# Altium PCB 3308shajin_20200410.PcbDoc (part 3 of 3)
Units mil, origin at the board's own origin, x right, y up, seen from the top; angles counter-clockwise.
Board outline 4724.41 x 2952.76 mil, 4 copper layers (Top, GND, Power, Bottom), stack 35.4 mil thick; 266 components, 266 nets, 1212 pads, 1516 vias.
Unrouted connection lines stored in the file: 149.
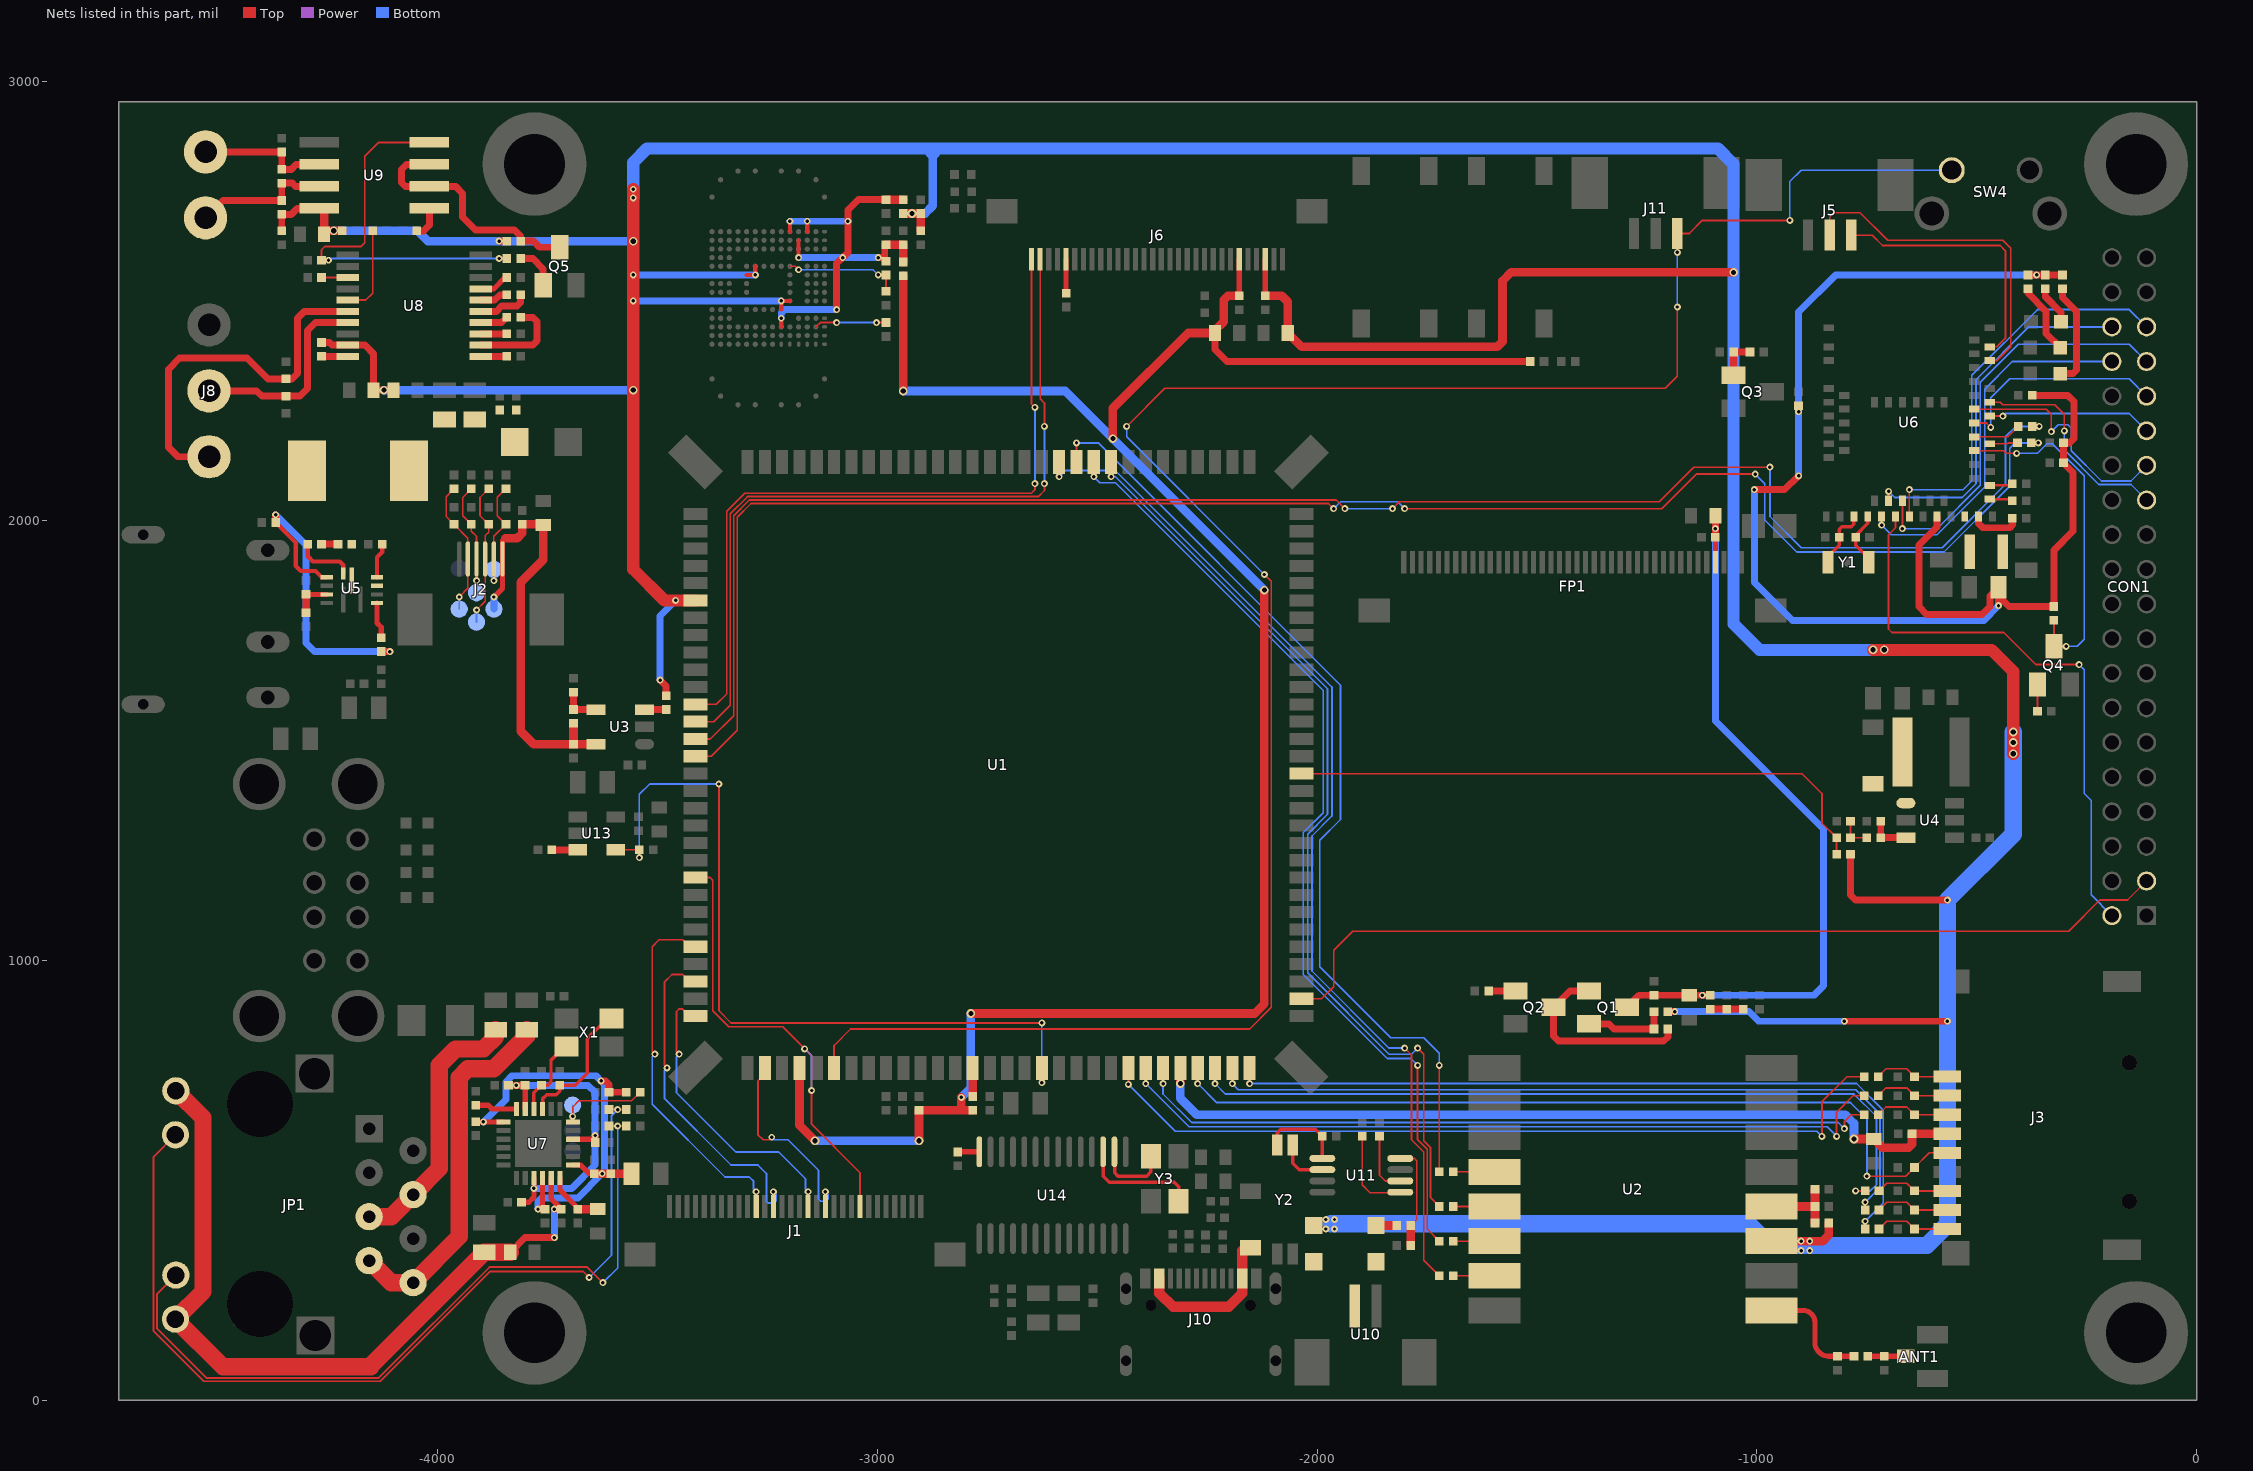
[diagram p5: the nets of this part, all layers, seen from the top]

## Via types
v1: diameter 15.75, hole 7.87, Top to Bottom, 1478 vias
v2: diameter 19.68, hole 11.81, Top to Bottom, 38 vias

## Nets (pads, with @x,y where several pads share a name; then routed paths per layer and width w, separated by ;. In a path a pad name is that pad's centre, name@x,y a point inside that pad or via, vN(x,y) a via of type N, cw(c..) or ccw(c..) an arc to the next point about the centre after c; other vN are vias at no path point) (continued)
MICP5: J1.11 U1.86 | length 837.2
  Top w3.94: v1(-3505.91,787.4) -3511.81,793.31 -3511.81,1031.83 -3496.4,1047.24 -3442.91,1047.24 -3427.17,1031.5 U1.86@-3413.39,1031.5 ; J1.11@-3275.59,440.94 v1(-3275.59,474.41)
  Bottom w3.94: v1(-3505.91,787.4) -3511.81,781.5 -3511.81,673.23 -3346.46,507.87 -3291.34,507.87 -3281.5,498.03 -3281.5,480.31 v1(-3275.59,474.41)
MICP6: J1.13 U1.88 | length 801.9
  Top w3.94: v1(-3478.35,755.91) -3484.25,761.81 -3484.25,951.13 -3466.87,968.5 -3442.91,968.5 -3427.17,952.76 U1.88@-3413.39,952.76 ; J1.13@-3236.22,440.94 v1(-3236.22,474.41)
  Bottom w3.94: v1(-3478.35,755.91) -3484.25,750 -3484.25,687.01 -3332.68,535.43 -3271.65,535.43 -3251.97,515.75 -3251.97,452.08 -3248.71,448.82 -3235.54,448.82 -3230.31,454.05 -3230.31,468.5 v1(-3236.22,474.41)
MICP7: J1.17 U1.90 | length 681.4
  Top w3.94: v1(-3450.79,787.4) -3456.69,793.31 -3456.69,884.26 -3451.19,889.76 -3442.91,889.76 -3427.17,874.02 U1.90@-3413.39,874.02 ; J1.17@-3157.48,440.94 v1(-3157.48,474.41)
  Bottom w3.94: v1(-3450.79,787.4) -3456.69,781.5 -3456.69,699.63 -3322.02,564.96 -3224.41,564.96 -3163.39,503.94 -3163.39,480.31 v1(-3157.48,474.41)
MICP8: J1.19 U1.92 | length 478
  Top w3.94: U1.92@-3255.91,755.91 -3255.91,742.13 -3271.65,726.38 -3271.65,604.33 -3259.84,592.52 -3246.06,592.52 v1(-3240.16,598.43) ; J1.19@-3118.11,440.94 v1(-3118.11,474.41)
  Bottom w3.94: v1(-3240.16,598.43) -3234.25,592.52 -3203.09,592.52 -3133.86,523.28 -3133.86,457.99 -3128.63,452.76 -3117.43,452.76 -3112.2,457.99 -3112.2,468.5 v1(-3118.11,474.41)
N18628326: R87.2 U14.14 | length 48.9
  Top w11.81: R87.2@-2816.93,564.96 -2816.54,565.35 U14.14@-2768.23,565.35
N18801307: R83.2 U13.3 | length 59.1
  Top w15.75: R83.2@-3740.16,1251.97 U13.3@-3681.1,1251.97
N20842578: Q2.1 R6.1 | length 61
  Top w15.75: R6.1@-1610.24,931.1 Q2.1@-1549.21,931.1
N20842606: Q1.1 Q2.3 R5.2 | length 447.7
  Top w15.75: Q1.1@-1381.89,931.1 -1425.2,931.1 Q2.3@-1462.6,893.7 -1462.6,828.74 -1450.79,816.93 -1212.6,816.93 -1202.76,826.77 R5.2@-1202.76,844.49
N20842653: Q1.2 R4.2 R5.1 | length 191.9
  Top w15.75: Q1.2@-1381.89,856.3 -1336.61,856.3 -1324.8,844.49 R5.1@-1234.25,844.49 R4.2@-1234.25,883.86
N77997198: D7.1 J3.8 R25.2 | length 169.5
  Top w3.94: R25.2@-722.44,433.07 -704.77,450.74 -659.45,450.74 D7.1@-641.78,433.07 J3.8@-567.54,433.07
N77997238: D6.1 J3.9 R26.2 | length 169.6
  Top w3.94: R26.2@-722.44,389.76 -704.72,407.48 -659.5,407.48 D6.1@-641.78,389.76 J3.9@-567.54,389.76
N77997484: D10.1 J3.3 R23.2 | length 171.5
  Top w3.94: R23.2@-724.41,649.61 -706.69,667.32 -659.5,667.32 D10.1@-641.78,649.61 J3.3@-567.54,649.61
N77997488: D12.1 J3.1 R21.2 | length 171.5
  Top w3.94: R21.2@-724.41,736.22 -706.69,753.94 -659.5,753.94 D12.1@-641.78,736.22 J3.1@-567.54,736.22
N77997499: D11.1 J3.2 R22.2 | length 171.5
  Top w3.94: R22.2@-724.41,692.91 -706.69,710.63 -659.5,710.63 D11.1@-641.78,692.91 J3.2@-567.54,692.91
N77997513: D8.1 J3.7 R24.2 | length 169.6
  Top w3.94: R24.2@-722.44,476.38 -704.72,494.09 -659.5,494.09 D8.1@-641.78,476.38 J3.7@-567.54,476.38
N80390256: D3.1 J2.5 P5.1 R14.2 | length 261.9
  Top w3.94: v1(-3872.05,1864.17) -3872.05,1912.43 J2.5@-3872.05,1913.39 -3872.05,1964.61 D3.1@-3844.49,1992.17 -3864.13,2011.81 -3864.13,2053.2 R14.2@-3844.49,2072.83
  Bottom w3.94: v1(-3872.05,1864.17) P5.1@-3872.05,1889.76
N80390258: D5.1 J2.4 P4.1 R12.2 | length 330.9
  Top w3.94: v1(-3911.42,1797.24) -3891.73,1816.93 -3891.73,1911.42 J2.4@-3891.73,1913.39 -3891.73,1966.54 -3883.86,1974.41 D5.1@-3883.86,1992.17 -3903.54,2011.86 -3903.54,2053.15 R12.2@-3883.86,2072.83
  Bottom w3.94: P4.1@-3911.42,1769.68 v1(-3911.42,1797.24)
N80390260: D4.1 J2.3 P3.1 R13.2 | length 257.4
  Top w3.94: R13.2@-3923.23,2072.83 -3942.91,2053.15 -3942.91,2011.86 D4.1@-3923.23,1992.17 -3923.23,1976.38 -3911.42,1964.57 J2.3@-3911.42,1913.39 -3911.42,1903.54 v1(-3911.42,1864.17)
  Bottom w3.94: P3.1@-3911.42,1836.61 v1(-3911.42,1864.17)
N80390262: D2.1 J2.2 P2.1 R11.2 | length 309.5
  Top w3.94: R11.2@-3962.6,2072.83 -3980.31,2055.12 -3980.31,2009.89 D2.1@-3962.6,1992.17 -3931.1,1960.68 -3931.1,1846.46 v1(-3950.79,1826.77)
  Bottom w3.94: P2.1@-3950.79,1799.21 v1(-3950.79,1826.77)
N80390735: CD3.2 RD1.1 RD2.1 U2.4 | length 175.2
  Top w19.68: U2.4@-966.54,440.94 CD3.2@-868.11,440.94 ; RD1.1@-868.11,403.54 CD3.2@-868.11,440.94 ; RD2.1@-868.11,480.31 CD3.2@-868.11,440.94
N80390797: ANT1.1 CD1.2 RW1.2 | length 86.6
  Top w11.81: RW1.2@-748.03,100.39 ANT1.1@-661.42,100.39
N80390810: CD2.2 RW1.1 U2.1 | length 266
  Top w11.81: U2.1@-966.54,204.72 -895.67,204.72 cw(c-895.67,177.17) -868.11,177.17 -868.11,131.89 ccw(c-836.61,131.89) -836.61,100.39 RW1.1@-779.53,100.39
N80390865: RW5.1 U2.12 | length 94.5
  Top w3.94: RW5.1@-1690.94,519.68 U2.12@-1596.46,519.68
N80390867: RW3.1 U2.14 | length 94.5
  Top w3.94: RW3.1@-1690.94,362.2 U2.14@-1596.46,362.2
N80390869: RW4.1 U2.13 | length 94.5
  Top w3.94: RW4.1@-1690.94,440.94 U2.13@-1596.46,440.94
N80390871: RW2.1 U2.15 | length 94.5
  Top w3.94: RW2.1@-1690.94,283.46 U2.15@-1596.46,283.46
N80396336: C18.1 R27.2 | length 37.4
  Top w15.75: R27.2@-4263.78,1946.85 C18.1@-4226.38,1946.85
N80396542: C20.1 C21.1 C22.1 C23.1 L2.2 R28.2 U5.5
N80396560: R29.1 R30.2 U5.11 | length 88.6
  Top w11.81: R30.2@-4299.21,1832.68 U5.11@-4251.97,1832.68
  Top w15.75: R29.1@-4299.21,1791.34 R30.2@-4299.21,1832.68
N80396572: C18.2 L2.1 U5.7
N80396580: R27.1 U5.8 | length 136.1
  Top w9.84: R27.1@-4295.28,1946.85 -4295.28,1919.29 -4283.46,1907.48 -4222.44,1907.48 -4214.57,1899.61 U5.8@-4214.57,1879.92
N80396618: R33.2 U5.3 | length 82.8
  Top w11.81: U5.3@-4137.8,1812.99 -4137.8,1767.72 -4127.95,1757.87 R33.2@-4127.95,1734.25
N80396635: C25.1 R33.1 U5.9 | length 755
  Top w9.84: C25.1@-4368.11,1996.06 -4322.83,1950.79 -4322.83,1897.64 -4311.02,1885.83 -4277.56,1885.83 -4263.78,1872.05 U5.9@-4251.97,1872.05
  Top w15.75: C25.1@-4368.11,1996.06 v1(-4368.11,2013.78) ; R33.1@-4127.95,1702.76 v1(-4108.27,1702.76)
  Bottom w15.75: v1(-4368.11,2013.78) -4299.21,1944.88 -4299.21,1722.44 -4279.53,1702.76 v1(-4108.27,1702.76)
N80398538: R44.1 U6.35 | length 52.8
  Top w5.91: U6.35@-470.47,2080.71 -423.23,2080.71 R44.1@-419.29,2084.65
N80398539: R45.1 U6.34 | length 57.9
  Top w5.91: U6.34@-470.47,2049.21 -417.32,2049.21 -419.29,2047.24 R45.1@-419.29,2045.28
N80398550: R46.1 U6.32 | length 114.8
  Top w15.75: U6.32@-496.06,2009.84 -496.06,1994.09 -486.22,1984.25 -425.2,1984.25 -419.29,1990.16 R46.1@-419.29,2005.91
N80398618: L3.2 U6.31
N80398679: Q3.1 R40.1 R41.1 | length 90.6
  Top w15.75: Q3.1@-1053.15,2330.71 R41.1@-1053.15,2383.86 R40.1@-1015.75,2383.86
N80413500: C15.2 R17.2 R18.1 | length 74.8
  Top w3.94: C15.2@-787.4,1316.93 R17.2@-787.4,1279.53 R18.1@-750,1279.53
N80413513: R15.1 R18.2 U4.3 | length 94.5
  Top w15.75: R15.1@-718.5,1316.93 R18.2@-718.5,1279.53 U4.3@-661.42,1279.53
N80413519: D1.1 L1.2 U4.1
N80422474: R77.2 R78.2 | length 264.1
  Top w3.94: -3198.82,2578.74 -3187.01,2578.74 v1(-3179.13,2570.87) ; v1(-2998.03,2559.06) R78.2@-2980.31,2559.06 R77.2@-2980.31,2521.65
  Bottom w3.94: v1(-3179.13,2570.87) -3009.84,2570.87 v1(-2998.03,2559.06)
N80422971: C64.2 | length 163.5
  Top w3.94: -3139.76,2440.94 -3129.92,2450.79 v1(-3092.52,2450.79) ; v1(-3001.97,2450.79) C64.2@-2980.31,2450.79
  Bottom w3.94: v1(-3092.52,2450.79) v1(-3001.97,2450.79)
N80425898: C56.2 U8.2 | length 216.8
  Top w15.75: U8.2@-3901.57,2399.61 -3783.46,2399.61 -3773.62,2409.45 -3773.62,2452.76 -3783.46,2462.6 C56.2@-3811.02,2462.6
N80425936: C56.1 U8.4 | length 63.9
  Top w15.75: U8.4@-3901.57,2450.79 -3854.33,2450.79 C56.1@-3842.52,2462.6
N80425956: C57.2 U8.5 | length 116.4
  Top w15.75: U8.5@-3901.57,2476.38 -3866.14,2476.38 -3854.33,2488.19 -3818.9,2488.19 -3811.02,2496.06 C57.2@-3811.02,2513.78
N80425958: C57.1 U8.6 | length 63.9
  Top w15.75: U8.6@-3901.57,2501.97 -3870.08,2501.97 -3858.27,2513.78 C57.1@-3842.52,2513.78
N80425978: C61.2 U8.7 | length 69.7
  Top w11.81: U8.7@-3901.57,2527.56 -3872.05,2527.56 -3846.46,2553.15 C61.2@-3842.52,2553.15
N80425980: C60.2 U8.3 | length 59.1
  Top w15.75: U8.3@-3901.57,2425.2 C60.2@-3842.52,2425.2
N80426078: R72.2 U8.20 | length 59.1
  Top w15.75: R72.2@-4263.78,2374.02 U8.20@-4204.72,2374.02
N80426086: R73.1 U8.1 | length 59.1
  Top w15.75: U8.1@-3901.57,2374.02 R73.1@-3842.52,2374.02
N80426264: Q5.3 R67.2 U9.2 U9.3 | length 556.8
  Top w15.75: U9.3@-4018.7,2810.43 -4070.87,2810.43 -4082.09,2799.21 -4082.09,2769.68 -4072.83,2760.43 U9.2@-4018.7,2760.43 -3958.66,2760.43 -3942.91,2744.68 -3942.91,2690.94 -3913.39,2661.42 -3824.8,2661.42 -3811.02,2647.64 R67.2@-3811.02,2635.83 -3781.5,2635.83 -3767.72,2622.05 Q5.3@-3722.44,2622.05
N80426293: Q5.1 R70.2 | length 98.4
  Top w15.75: R70.2@-3811.02,2596.46 -3783.46,2596.46 -3759.84,2572.83 Q5.1@-3759.84,2535.43
N80433973: J6.26 R62.1 | length 76.8
  Top w11.81: R62.1@-2570.87,2517.72 J6.26@-2570.87,2594.49
N80440547: C33.2 JP1.7 JP1.8 | length 837
  Top w39.37: JP1.7@-4155.65,317.84 -4105.65,267.83 JP1.8@-4055.65,267.83 -3950.79,372.69 -3950.79,734.25 -3931.1,753.94 -3872.05,753.94 -3797.24,828.74 C33.2@-3797.24,842.52
N80440563: C32.2 JP1.4 JP1.5 | length 610
  Top w39.37: JP1.5@-4155.65,417.83 -4105.65,417.83 JP1.4@-4055.65,467.83 -3996.06,527.42 -3996.06,761.81 -3958.66,799.21 -3895.67,799.21 -3868.11,826.77 C32.2@-3868.11,842.52
N80440687: JP1.10 R55.2 R56.2 | length 2061.9
  Top w3.94: JP1.10@-4596.02,603.94 -4645.67,554.29 -4645.67,157.48 -4531.5,43.31 -4129.92,43.31 -3879.92,293.31 -3669.29,293.31 v1(-3655.51,279.53) ; R55.2@-3610.24,661.42 v1(-3590.55,661.42) R56.2@-3570.87,661.42
  Bottom w3.94: v1(-3655.51,279.53) -3604.33,330.71 -3604.33,647.64 v1(-3590.55,661.42)
N80441317: JP1.11 R52.2 R53.2 | length 1728.1
  Top w3.94: JP1.11@-4595.02,284.94 -4637.8,242.17 -4637.8,163.39 -4525.59,51.18 -4133.86,51.18 -3881.89,303.15 -3659.45,303.15 v1(-3624.02,267.72) ; R53.2@-3610.24,624.02 v1(-3590.55,624.02) R52.2@-3570.87,624.02
  Bottom w3.94: v1(-3624.02,267.72) -3590.55,301.18 v1(-3590.55,624.02)
N80460455: C6.2 C9.1 U3.4 | length 90.5
  Top w15.75: C9.1@-3690.94,1610.24 C6.2@-3690.94,1570.87 U3.4@-3639.77,1570.87
N80460749: R9.2 U3.3 | length 49.2
  Top w15.75: U3.3@-3529.53,1570.87 R9.2@-3480.31,1570.87
N80464235: C62.2 U11.1 Y2.1 | length 190.1
  Top w7.87: Y2.1@-2090.94,580.71 -2090.94,607.87 -2082.68,616.14 -2003.94,616.14 C62.2@-1988.19,600.39 U11.1@-1988.19,550.2
N80464249: U11.2 Y2.2 | length 114.8
  Top w7.87: Y2.2@-2055.51,580.71 -2055.51,539.37 -2040.75,524.61 U11.2@-1988.19,524.61
N80464317: D13.2 D14.2 R74.2 | length 47.2
  Top w19.68: D13.2@-1866.14,397.64 R74.2@-1818.9,397.64
N80464332: D14.1 U10.2
N80464365: R75.1 U11.6 | length 141.1
  Top w3.94: R75.1@-1858.27,600.39 -1858.27,511.81 -1845.47,499.01 U11.6@-1811.03,499.01
N80464367: R76.1 U11.5 | length 204.6
  Top w3.94: R76.1@-1897.64,600.39 -1897.64,490.16 -1879.92,472.44 -1812.01,472.44 U11.5@-1811.03,473.42
N80464535: C63.1 R74.1 U11.8 | length 238.1
  Top w3.94: U11.8@-1811.03,550.2 -1778.55,550.2 -1773.62,545.28 -1773.62,411.42 R74.1@-1787.4,397.64
  Top w19.68: C63.1@-1787.4,352.36 R74.1@-1787.4,397.64
N803989560: LED3.1 R38.1 | length 238
  Top w15.75: LED3.1@-310.3,2334.59 -310.24,2334.65 -281.5,2334.65 -273.62,2342.52 -273.62,2476.38 -305.12,2507.87 R38.1@-305.12,2527.56
N803993010: Q4.1 R48.1 | length 61
  Top w3.94: R48.1@-362.2,1566.93 Q4.1@-362.2,1627.95
N803993870: LED2.1 R37.1 | length 164.4
  Top w15.75: R37.1@-383.86,2527.56 -383.86,2517.72 -342.52,2476.38 -342.52,2425.86 LED2.1@-310.3,2393.64
N803996680: LED1.1 R36.1 | length 89.8
  Top w15.75: R36.1@-344.49,2527.56 -344.49,2509.84 -308.33,2473.68 LED1.1@-308.33,2452.7
P0.4: CON1.34 U6.20 | length 845.7
  Top w3.94: v1(-716.54,1990.16) U6.20@-716.54,2009.84
  Bottom w3.94: v1(-716.54,1990.16) -694.88,1968.5 -590.55,1968.5 -482.28,2076.77 -482.28,2299.21 -419.29,2362.2 -332.68,2362.2 CON1.34@-192.91,2362.2
P0.5: CON1.36 U6.21 | length 834.2
  Top w3.94: U6.21@-700.79,2045.28 v1(-700.79,2066.93)
  Bottom w3.94: v1(-700.79,2066.93) -687.01,2053.15 -533.46,2053.15 -501.97,2084.65 -501.97,2320.87 -381.89,2440.94 -332.68,2440.94 CON1.36@-192.91,2440.94
P0.6: CON1.2 U6.22 | length 1330.8
  Top w3.94: U6.22@-685.04,2009.84 -685.04,1984.25 -700.79,1968.5 -700.79,1753.94 -692.91,1746.06 -438.98,1746.06 -366.14,1673.23 v1(-267.72,1673.23)
  Bottom w3.94: v1(-267.72,1673.23) -255.91,1661.42 -255.91,1379.92 -240.16,1364.17 -240.16,1149.61 CON1.2@-192.91,1102.36
P0.7: CON1.33 U6.23 | length 945.3
  Top w3.94: v1(-669.29,1982.28) U6.23@-669.29,2045.28
  Bottom w3.94: v1(-669.29,1982.28) -590.55,1982.28 -492.13,2080.71 -492.13,2314.96 -405.51,2401.57 -153.54,2401.57 CON1.33@-114.17,2362.2
P0.8: CON1.35 U6.24 | length 927
  Top w3.94: U6.24@-653.54,2009.84 v1(-653.54,2070.87)
  Bottom w3.94: v1(-653.54,2070.87) -531.5,2070.87 -511.81,2090.55 -511.81,2330.71 -362.2,2480.31 -153.54,2480.31 CON1.35@-114.17,2440.94
PANELVCC#: C2.1 C3.1 C4.1 C5.1 FP1.4 Q1.3 R10.1 | length 1732.5
  Top w11.81: FP1.4@-1094.49,1905.51 C3.1@-1094.49,1962.6
  Top w15.75: Q1.3@-1295.28,893.7 -1267.72,921.26 C5.1@-1234.25,921.26 v1(-1124.02,921.26) R10.1@-1106.3,921.26 ; C3.1@-1094.49,1962.6 v1(-1094.49,1982.28) C2.1@-1094.49,2011.81
  Bottom w15.75: v1(-1124.02,921.26) -870.08,921.26 -848.43,942.91 -848.43,1299.21 -1094.49,1545.28 v1(-1094.49,1982.28)
PHONE_DET: J1.23 U1.82 | length 994.1
  Top w3.94: U1.82@-3413.39,1188.98 -3379.92,1188.98 -3374.02,1183.07 -3374.02,885.83 -3337.6,849.41 -3215.55,849.41 v1(-3165.35,799.21) ; v1(-3149.61,704.72) -3149.61,627.95 -3039.37,517.72 J1.23@-3039.37,440.94
  Power w3.94: v1(-3165.35,799.21) -3149.61,783.46 v1(-3149.61,704.72)
PWM3/GPIO0_C0/IR_RX: R17.1 R19.1 U1.15 | length 1353.5
  Top w3.94: U1.15@-2035.43,1425.2 -897.64,1425.2 -852.36,1379.92 -852.36,1312.99 R17.1@-818.9,1279.53 R19.1@-818.9,1242.13
RESET: J11.1 SW4.2 U1.96 | length 4897.7
  Top w3.94: U1.96@-3098.43,755.91 -3098.43,807.09 -3061.02,844.49 -2153.54,844.49 -2104.33,893.7 -2104.33,1862.2 v1(-2120.08,1877.95) ; v1(-2433.07,2214.57) -2346.46,2301.18 -1208.66,2301.18 -1181.1,2328.74 v1(-1181.1,2486.22) ; v1(-1181.1,2610.24) J11.1@-1181.1,2653.54 -1153.54,2653.54 -1124.02,2683.07 v1(-925.2,2683.07)
  Bottom w3.94: v1(-2433.07,2214.57) -2433.07,2190.94 v1(-2120.08,1877.95) ; v1(-1181.1,2486.22) v1(-1181.1,2610.24) ; v1(-925.2,2683.07) -925.2,2771.65 -899.61,2797.24 SW4.2@-557.09,2797.24
RESET_LED: C10.1 R7.2 R10.2 | length 74.8
  Top w15.75: R10.2@-1106.3,889.76 R7.2@-1031.5,889.76
RS485_A: J7.1 R68.2 R69.1 U9.7 | length 317.6
  Top w15.75: J7.1@-4527.56,2688.98 -4488.19,2728.35 R68.2@-4354.33,2728.35 R69.1@-4354.33,2767.72 -4330.12,2767.72 -4322.83,2760.43 U9.7@-4268.7,2760.43
RS485_B: J7.2 R69.2 R71.1 U9.6 | length 303
  Top w15.75: J7.2@-4527.56,2838.98 -4527.17,2838.58 R71.1@-4354.33,2838.58 R69.2@-4354.33,2799.21 -4332.68,2799.21 -4321.46,2810.43 U9.6@-4268.7,2810.43
RSET: R54.2 U7.24 | length 96.5
  Top w11.81: R54.2@-3913.39,671.26 -3884.34,671.26 -3875.98,662.9 U7.24@-3820.38,662.9
RXC: R66.1 U9.1 | length 72
  Top w15.75: R66.1@-4047.24,2659.45 -4031.5,2659.45 -4018.7,2672.24 U9.1@-4018.7,2710.43
RXD: R64.1 U8.15 | length 205.3
  Top w3.94: U8.15@-4204.72,2501.97 -4163.39,2501.97 -4147.64,2517.72 R64.1@-4147.64,2659.45
SPDIF_TX: CON1.3 U1.2 | length 2080.6
  Top w3.94: U1.2@-2035.43,913.39 -1990.16,913.39 -1962.6,940.94 -1962.6,1023.62 -1919.29,1066.93 -291.34,1066.93 -220.47,1137.8 -157.48,1137.8 CON1.3@-114.17,1181.1
SPI2_CLK: RW5.2 U1.41 | length 2154.2
  Top w3.94: U1.41@-2547.24,2133.86 v1(-2547.24,2177.17) ; RW5.2@-1722.44,519.68 v1(-1722.44,761.81)
  Bottom w3.94: v1(-2547.24,2177.17) -2498.03,2177.17 -1946.85,1625.98 -1946.85,1320.87 -1994.09,1273.62 -1994.09,986.22 -1832.68,824.8 -1757.87,824.8 -1722.44,789.37 v1(-1722.44,761.81)
SPI2_CS: RW2.2 U1.42 | length 2361
  Top w3.94: v1(-2586.61,2100.39) U1.42@-2586.61,2133.86 ; v1(-1801.18,801.18) -1785.43,785.43 -1785.43,592.52 -1757.87,564.96 -1757.87,318.9 RW2.2@-1722.44,283.46
  Bottom w3.94: v1(-2586.61,2100.39) -2572.83,2114.17 -2458.66,2114.17 -1966.54,1622.05 -1966.54,1328.74 -2011.81,1283.46 -2011.81,976.38 -1836.61,801.18 v1(-1801.18,801.18)
SPI2_RX/UART2_RX_M0: RW4.2 U1.39 | length 2102.8
  Top w3.94: v1(-2468.5,2100.39) U1.39@-2468.5,2133.86 ; v1(-1771.65,801.18) -1757.87,787.4 -1757.87,590.55 -1742.13,574.8 -1742.13,460.63 RW4.2@-1722.44,440.94
  Bottom w3.94: v1(-2468.5,2100.39) -2458.66,2100.39 -1976.38,1618.11 -1976.38,1332.68 -2021.65,1287.4 -2021.65,972.44 -1836.61,787.4 -1785.43,787.4 v1(-1771.65,801.18)
SPI2_TX/UART2_TX_M0: RW3.2 U1.40 | length 2186.4
  Top w3.94: v1(-2507.87,2100.39) U1.40@-2507.87,2133.86 ; v1(-1771.65,761.81) -1771.65,592.52 -1750,570.87 -1750,389.76 RW3.2@-1722.44,362.2
  Bottom w3.94: v1(-2507.87,2100.39) -2494.09,2086.61 -2458.66,2086.61 -1986.22,1614.17 -1986.22,1336.61 -2031.5,1291.34 -2031.5,968.5 -1840.55,777.56 -1787.4,777.56 v1(-1771.65,761.81)
SPISDI/XTALDET: R60.1 TP6.1 U7.18 | length 227.1
  Top w3.94: U7.18@-3692.43,633.37 -3692.43,645.19 v1(-3692.91,645.67) -3692.91,667.32 -3679.13,681.1 -3559.06,681.1 R60.1@-3539.37,700.79
  Bottom w3.94: v1(-3692.91,645.67) TP6.1@-3692.91,671.26
SWDCLK: J5.1 U6.53 | length 607.5
  Top w3.94: J5.1@-785.43,2649.61 -738.19,2649.61 -714.57,2625.98 -446.85,2625.98 -435.04,2614.17 -435.04,2415.35 -454.72,2395.67 U6.53@-470.47,2395.67
SWDIO: J5.2 U6.51 | length 775
  Top w3.94: J5.2@-834.65,2649.61 -834.65,2690.94 -824.8,2700.79 -765.75,2700.79 -702.76,2637.8 -440.94,2637.8 -423.23,2620.08 -423.23,2395.67 -454.72,2364.17 U6.51@-470.47,2364.17
TF_CLK: D9.1 J3.5 U1.117 | length 1924.9
  Top w3.94: v1(-2271.65,720.47) U1.117@-2271.65,755.91 ; v1(-750,509.84) -661.46,509.84 D9.1@-641.78,529.53 -608.31,562.99 J3.5@-567.54,562.99
  Bottom w3.94: v1(-2271.65,720.47) -2228.35,677.17 -787.4,677.17 -750,639.76 v1(-750,509.84)
TF_CMD: R23.1 U1.115 | length 1708.4
  Top w3.94: v1(-2350.39,720.47) U1.115@-2350.39,755.91 ; v1(-801.18,618.11) -801.18,633.86 -785.43,649.61 R23.1@-755.91,649.61
  Bottom w3.94: v1(-2350.39,720.47) -2350.39,696.85 -2285.43,631.89 -814.96,631.89 v1(-801.18,618.11)
TF_D0: R24.1 U1.118 | length 1800.5
  Top w3.94: v1(-2232.28,720.47) U1.118@-2232.28,755.91 ; v1(-775.59,476.38) R24.1@-753.94,476.38
  Bottom w3.94: v1(-2232.28,720.47) -2208.66,696.85 -779.53,696.85 -728.35,645.67 -728.35,490.16 -742.13,476.38 v1(-775.59,476.38)
TF_D1: R25.1 U1.119 | length 1768.8
  Top w3.94: v1(-2192.91,720.47) U1.119@-2192.91,755.91 ; R25.1@-753.94,433.07 v1(-753.94,450.79)
  Bottom w3.94: v1(-2192.91,720.47) -2179.13,706.69 -775.59,706.69 -720.47,651.57 -720.47,484.25 v1(-753.94,450.79)
TF_D2: R21.1 U1.113 | length 1861.9
  Top w3.94: v1(-2429.13,718.5) U1.113@-2429.13,755.91 ; v1(-852.36,600.39) -852.36,679.13 -795.28,736.22 R21.1@-755.91,736.22
  Bottom w3.94: v1(-2429.13,718.5) -2322.83,612.2 -864.17,612.2 v1(-852.36,600.39)
TF_D3: R22.1 U1.114 | length 1789.6
  Top w3.94: v1(-2389.76,720.47) U1.114@-2389.76,755.91 ; v1(-818.9,600.39) -818.9,655.51 -781.5,692.91 R22.1@-755.91,692.91
  Bottom w3.94: v1(-2389.76,720.47) -2291.34,622.05 -840.55,622.05 v1(-818.9,600.39)
TF_DET: R26.1 U1.120 | length 1788.5
  Top w3.94: v1(-2153.54,720.47) U1.120@-2153.54,755.91 ; R26.1@-753.94,389.76 v1(-753.94,407.48)
  Bottom w3.94: v1(-2153.54,720.47) -773.62,720.47 -712.6,659.45 -712.6,448.82 v1(-753.94,407.48)
TF_VCC: C16.1 C17.1 J3.4 U1.116 | length 1906.5
  Top w19.68: v2(-2311.02,720.47) U1.116@-2311.02,755.91 ; v2(-779.53,594.49) C17.1@-734.25,594.49 -714.57,574.8 -655.51,574.8 -647.64,582.68 C16.1@-647.64,606.3 J3.4@-567.54,606.3
  Bottom w19.68: v2(-2311.02,720.47) -2311.02,687.01 -2273.62,649.61 -799.21,649.61 -779.53,629.92 v2(-779.53,594.49)
TXC: R65.1 R70.1 U9.4 | length 908.2
  Top w3.94: v1(-4248.03,2592.52) R65.1@-4263.78,2592.52 -4263.78,2616.14 -4255.91,2624.02 -4173.23,2624.02 -4165.35,2631.89 -4165.35,2828.94 -4133.86,2860.43 U9.4@-4018.7,2860.43 ; v1(-3860.24,2596.46) R70.1@-3842.52,2596.46
  Bottom w3.94: v1(-4248.03,2592.52) -4244.09,2596.46 v1(-3860.24,2596.46)
TXD: R63.1 U8.13 | length 59.1
  Top w3.94: R63.1@-4263.78,2553.15 U8.13@-4204.72,2553.15
UART0_CTS/SPI0_CLK/I2C2_SDA: J6.29 U1.73 | length 1795.5
  Top w3.94: U1.73@-3413.39,1543.31 -3372.05,1543.31 -3334.65,1580.71 -3334.65,2015.75 -3295.28,2055.12 -2633.86,2055.12 -2620.08,2068.9 v1(-2620.08,2084.65) ; J6.29@-2629.92,2594.49 -2629.92,2277.56 -2620.08,2267.72 v1(-2620.08,2214.57)
  Bottom w3.94: v1(-2620.08,2084.65) v1(-2620.08,2214.57)
UART0_RTS/SPI0_CSN/I2C2_SCL: J6.30 U1.72 | length 1744.1
  Top w3.94: U1.72@-3413.39,1582.68 -3366.14,1582.68 -3342.52,1606.3 -3342.52,2021.65 -3301.18,2062.99 -2649.61,2062.99 -2641.73,2070.87 v1(-2641.73,2084.65) ; J6.30@-2649.61,2594.49 -2649.61,2265.75 v1(-2641.73,2257.87)
  Bottom w3.94: v1(-2641.73,2084.65) v1(-2641.73,2257.87)
UART0_RX/SPI0_RX: R43.1 U1.75 | length 3916.5
  Top w3.94: U1.75@-3413.39,1464.57 -3377.95,1464.57 -3318.9,1523.62 -3318.9,2007.87 -3287.4,2039.37 -1974.41,2039.37 v1(-1962.6,2027.56) ; v1(-1801.18,2027.56) -1216.54,2027.56 -1137.8,2106.3 v1(-1003.94,2106.3) ; R43.1@-375.98,2177.17 v1(-360.24,2177.17)
  Bottom w3.94: v1(-1962.6,2027.56) -1946.85,2043.31 -1816.93,2043.31 v1(-1801.18,2027.56) ; v1(-1003.94,2106.3) -982.28,2084.65 -982.28,2001.97 -909.45,1929.13 -574.8,1929.13 -425.2,2078.74 -425.2,2165.35 -413.39,2177.17 v1(-360.24,2177.17)
UART0_TX/SPI0_TX: R42.1 U1.74 | length 3928.7
  Top w3.94: U1.74@-3413.39,1503.94 -3379.92,1503.94 -3326.77,1557.09 -3326.77,2011.81 -3291.34,2047.24 -1956.69,2047.24 v1(-1937.01,2027.56) ; v1(-1828.74,2027.56) -1812.99,2043.31 -1222.44,2043.31 -1143.7,2122.05 v1(-970.47,2122.05) ; R42.1@-374.02,2214.57 v1(-358.27,2214.57)
  Bottom w3.94: v1(-1937.01,2027.56) v1(-1828.74,2027.56) ; v1(-970.47,2122.05) -970.47,2009.84 -899.61,1938.98 -578.74,1938.98 -435.04,2082.68 -435.04,2190.94 -411.42,2214.57 v1(-358.27,2214.57)
UART1_RX_RS232_COM1: ED6.1 J8.1 U8.16 | length 853.7
  Top w15.75: J8.1@-4519.69,2145.67 -4590.55,2145.67 -4612.2,2167.32 -4612.2,2344.49 -4586.61,2370.08 -4433.07,2370.08 -4385.87,2322.88 ED6.1@-4344.49,2322.88 -4344.44,2322.83 -4330.71,2322.83 -4318.9,2334.65 -4318.9,2460.63 -4303.15,2476.38 U8.16@-4204.72,2476.38
UART1_TX_RS232_COM1: ED5.1 J8.2 U8.17 | length 466.6
  Top w15.75: J8.2@-4519.69,2295.67 -4411.81,2295.67 -4399.56,2283.42 ED5.1@-4344.49,2283.42 -4313.04,2283.42 -4295.28,2301.18 -4295.28,2433.07 -4277.56,2450.79 U8.17@-4204.72,2450.79
USB_DRV: R82.2 U1.108 U13.4 | length 1836.2
  Top w3.94: U13.4@-3594.49,1251.97 R82.2@-3541.34,1251.97 v1(-3541.34,1234.25) ; v1(-3360.24,1401.57) -3360.24,885.83 -3332.68,858.27 v1(-2625.98,858.27) ; v1(-2625.98,722.44) U1.108@-2625.98,755.91
  Bottom w3.94: v1(-3541.34,1234.25) -3541.34,1377.95 -3517.72,1401.57 v1(-3360.24,1401.57) ; v1(-2625.98,722.44) v1(-2625.98,858.27)
USB_ID: R2.2 U1.104 | length 65
  Top w19.68: R2.2@-2783.46,690.94 U1.104@-2783.46,755.91
USBVBUS: D15.1 J10.A4 J10.A9 J10.B4 J10.B9 | length 360.3
  Top w23.62: J10.A4@-2359.06,277.56 -2359.06,244.09 -2327.56,212.6 -2200.79,212.6 -2170.08,243.31 J10.B4@-2170.08,277.56 -2170.08,340.35 D15.1@-2159.45,350.98
VCC1: C28.1 L3.1 R36.2 R37.2 R38.2 R39.2 R47.2 R49.1 R50.1 R51.2 U6.28 | length 3227.6
  Top w15.75: v1(-1005.91,2070.87) -937.01,2070.87 v1(-905.51,2102.36) ; v1(-905.51,2248.03) R39.2@-905.51,2261.81 ; U6.28@-590.55,2009.84 -590.55,1986.22 -631.89,1944.88 -631.89,1805.12 -614.17,1787.4 -488.19,1787.4 -470.47,1805.12 -470.47,1828.74 C28.1@-450.79,1848.43 ; v1(-450.79,1807.09) C28.1@-450.79,1848.43 ; R37.2@-383.86,2559.06 v1(-364.17,2559.06) R38.2@-305.12,2559.06 ; R51.2@-374.02,2285.43 -293.31,2285.43 -279.53,2271.65 -279.53,2187.01 -289.37,2177.17 R50.1@-303.15,2177.17 R49.1@-303.15,2131.89 -281.5,2110.24 -281.5,1976.38 -324.8,1933.07 R47.2@-324.8,1805.12 -427.17,1805.12 -442.91,1820.87 -442.91,1840.55 C28.1@-450.79,1848.43
  Bottom w15.75: v1(-1005.91,2070.87) -1005.91,1860.24 -919.29,1773.62 -484.25,1773.62 v1(-450.79,1807.09) ; v1(-905.51,2102.36) v1(-905.51,2248.03) -905.51,2474.41 -820.87,2559.06 v1(-364.17,2559.06)
VCC3V3_SYS: C49.1 C50.1 C53.1 C54.1 C55.1 C58.1 C59.1 C68.1 C69.1 D13.1 J6.3 R4.1 R9.1 R19.2 R67.1 R68.1 R72.1 R80.1 RD1.2 U1.66 U2.3 U8.19 U9.8 | length 13788.6
  Top w9.84: -3297.24,2559.06 v1(-3277.56,2559.06) -3277.56,2578.74 ; -3218.5,2480.31 v1(-3218.5,2500) -3198.82,2500
  Top w11.81: C50.1@-2118.11,2511.81 J6.3@-2118.11,2594.49
  Top w15.75: C55.1@-4354.33,2659.45 R68.1@-4354.33,2696.85 -4332.68,2696.85 -4319.09,2710.43 -4285.43,2710.43 U9.8@-4268.7,2710.43 ; R72.1@-4263.78,2405.51 -4246.06,2405.51 -4240.16,2399.61 U8.19@-4204.72,2399.61 -4165.35,2399.61 -4145.67,2379.92 C53.1@-4145.67,2297.24 v2(-4122.05,2297.24) C54.1@-4100.39,2297.24 ; v1(-3860.24,2635.83) R67.1@-3842.52,2635.83 ; v1(-3494.09,1637.8) -3480.31,1624.02 R9.1@-3480.31,1602.36 ; R4.1@-1202.76,883.86 v1(-1187.01,883.86) ; v1(-801.18,862.2) v1(-566.93,862.2) ; R19.2@-787.4,1242.13 -787.4,1149.61 -775.59,1137.8 v1(-566.93,1137.8)
  Top w19.68: U9.8@-4268.7,2710.43 -4257.87,2710.43 C58.1@-4257.87,2651.57 -4250,2659.45 v2(-4236.22,2659.45) C59.1@-4216.54,2659.45 ; R80.1@-2940.94,2698.82 v2(-2921.26,2698.82) C69.1@-2901.57,2698.82 C68.1@-2901.57,2659.45 ; C50.1@-2118.11,2511.81 -2080.71,2511.81 -2066.93,2498.03 C49.1@-2066.93,2427.17 -2035.43,2395.67 -1590.55,2395.67 -1578.74,2407.48 -1578.74,2545.28 -1559.06,2564.96 v2(-1053.15,2564.96) ; U2.3@-966.54,362.2 v1(-899.61,362.2) v1(-879.92,362.2) -850.39,362.2 -836.61,375.98 RD1.2@-836.61,403.54
  Top w27.56: v1(-3555.12,2753.94) v1(-3555.12,2734.25) v2(-3555.12,2635.83) v1(-3555.12,2559.06) v1(-3555.12,2500) v2(-3555.12,2297.24) -3555.12,1889.76 -3484.25,1818.9 v1(-3458.66,1818.9) U1.66@-3413.39,1818.9 ; v2(-736.22,1706.69) v2(-710.63,1706.69) -466.54,1706.69 -417.32,1657.48 v2(-417.32,1519.68) v2(-417.32,1496.06) v2(-417.32,1470.47)
  Bottom w3.94: v1(-1980.31,389.76) -1968.5,401.57 ; v1(-899.61,340.55) -889.76,350.39 -889.76,352.36
  Bottom w7.87: -889.76,352.36 -879.92,342.52 v1(-879.92,340.55)
  Bottom w15.75: v1(-3555.12,2500) v1(-3218.5,2500) ; v1(-3555.12,2559.06) v1(-3277.56,2559.06) ; v1(-3494.09,1637.8) -3494.09,1783.46 v1(-3458.66,1818.9) ; v1(-1187.01,883.86) -1017.72,883.86 -996.06,862.2 v1(-801.18,862.2)
  Bottom w19.68: v2(-4236.22,2659.45) -4045.28,2659.45 -4021.65,2635.83 v1(-3860.24,2635.83) v2(-3555.12,2635.83) ; v2(-4122.05,2297.24) v2(-3555.12,2297.24) ; v2(-2921.26,2698.82) -2891.73,2698.82 -2874.02,2716.54 -2874.02,2828.74 ; -2891.73,2846.46 -2874.02,2828.74 ; -2874.02,2846.46 -2874.02,2828.74 ; -2856.3,2846.46 -2874.02,2828.74
  Bottom w27.56: v1(-3555.12,2734.25) v1(-3555.12,2753.94) -3555.12,2814.96 -3523.62,2846.46 -2891.73,2846.46 -2874.02,2846.46 -2856.3,2846.46 -1088.58,2846.46 -1053.15,2811.02 v2(-1053.15,2564.96) -1053.15,1765.75 -994.09,1706.69 v2(-736.22,1706.69) v2(-710.63,1706.69)
  Bottom w39.37: -1968.5,401.57 -1019.69,401.57 -970.47,352.36 -889.76,352.36 -614.17,352.36 -566.93,399.61 v1(-566.93,862.2) v1(-566.93,1137.8) -417.32,1287.4 v2(-417.32,1470.47) v2(-417.32,1496.06) v2(-417.32,1519.68)
  other v1: -1960.63,389.76 -1980.31,411.42 -1960.63,411.42
VCC_1V8: C51.1 C52.1 J6.6 R1.1 R2.1 R32.1 R79.1 U1.94 | length 5066.7
  Top w11.81: C51.1@-2177.17,2511.81 J6.6@-2177.17,2594.49
  Top w15.75: C52.1@-2232.28,2427.17 -2232.28,2389.76 -2204.72,2362.2 R32.1@-1515.75,2362.2
  Top w19.68: U1.94@-3177.17,755.91 -3177.17,625.98 v2(-3141.73,590.55) ; v2(-2940.94,2295.28) R79.1@-2940.94,2557.09 ; v2(-2905.51,590.55) R1.1@-2905.51,659.45 -2809.06,659.45 ; v1(-2809.06,688.98) -2809.06,659.45 ; v2(-2787.4,879.92) -2141.73,879.92 -2120.08,901.57 v2(-2120.08,1842.52) ; R2.1@-2783.46,659.45 -2809.06,659.45 ; v2(-2464.57,2187.01) -2464.57,2255.91 -2293.31,2427.17 C52.1@-2232.28,2427.17 -2232.28,2433.07 -2212.6,2452.76 -2212.6,2501.97 -2202.76,2511.81 C51.1@-2177.17,2511.81
  Bottom w19.68: v2(-3141.73,590.55) v2(-2905.51,590.55) ; v2(-2940.94,2295.28) -2572.83,2295.28 v2(-2464.57,2187.01) v2(-2120.08,1842.52) ; v1(-2809.06,688.98) -2787.4,710.63 v2(-2787.4,879.92)
VCC_1V8_S3: C65.1 C66.1 C67.1 R78.1 R79.2 R80.2 | length 1068.5
  Top w9.84: -3218.5,2440.94 v1(-3218.5,2460.63) ; -3198.82,2657.48 v1(-3198.82,2681.1) ; v1(-3179.13,2598.43) -3179.13,2637.8 ; -3159.45,2657.48 v1(-3159.45,2681.1)
  Top w15.75: v1(-3092.52,2480.31) -3092.52,2584.65 v1(-3078.74,2598.43) -3066.93,2610.24 v1(-3066.93,2681.1) -3066.93,2706.69 -3043.31,2730.31 C67.1@-2980.31,2730.31 ; v1(-2998.03,2598.43) -2988.19,2598.43 R78.1@-2983.27,2593.5 ; R78.1@-2980.31,2590.55 R78.1@-2983.27,2593.5 ; C65.1@-2980.31,2627.95 -2983.27,2625 R78.1@-2983.27,2593.5
  Top w19.68: C65.1@-2980.31,2627.95 C66.1@-2940.94,2627.95 R79.2@-2940.94,2588.58 ; C67.1@-2980.31,2730.31 R80.2@-2940.94,2730.31
  Bottom w15.75: v1(-3218.5,2460.63) -3218.5,2472.44 -3210.63,2480.31 v1(-3092.52,2480.31) ; v1(-3198.82,2681.1) v1(-3159.45,2681.1) v1(-3066.93,2681.1) ; v1(-3179.13,2598.43) v1(-3078.74,2598.43) v1(-2998.03,2598.43)
VCC_LDO5V: C24.1 U5.6 | length 79.7
  Top w9.84: U5.6@-4137.8,1872.05 -4137.8,1917.32 -4125.98,1929.13 C24.1@-4125.98,1946.85
VCC_TP: C6.1 C8.1 C12.1 C14.1 J2.6 P6.1 U3.5 | length 1003.6
  Top w3.94: J2.6@-3852.36,1909.45 J2.6@-3852.36,1913.39
  Top w11.81: v1(-3872.05,1826.77) -3852.36,1846.46 J2.6@-3852.36,1909.45 ; J2.6@-3852.36,1913.39 -3852.36,1954.72 -3846.46,1960.63
  Top w19.68: -3846.46,1960.63 -3818.9,1960.63 -3807.09,1972.44 C12.1@-3807.09,1992.13 C14.1@-3759.84,1992.13 ; C14.1@-3759.84,1990.16 -3759.84,1911.42 -3811.02,1860.24 -3811.02,1521.65 -3781.5,1492.13 C8.1@-3690.94,1492.13 ; C6.1@-3690.94,1539.37 C8.1@-3690.94,1492.13 ; U3.5@-3639.77,1492.13 C8.1@-3690.94,1492.13
  Bottom w15.75: P6.1@-3872.05,1799.21 v1(-3872.05,1826.77)
VDD5: C47.1 C48.1 JP1.9 JP1.12 R61.1 U7.11 | length 1772.8
  Top w11.81: U7.11@-3741.64,505.42 -3741.64,458.18 -3726.38,442.91 C48.1@-3718.5,435.04
  Top w15.75: R61.1@-3834.65,336.61 -3801.18,370.08 v1(-3734.25,370.08) ; v1(-3734.25,435.04) C48.1@-3718.5,435.04
  Top w39.37: JP1.9@-4595.02,703.94 -4533.46,642.39 -4533.46,247.5 JP1.12@-4596.02,184.94 -4487.84,76.77 -4151.57,76.77 -4151.57,78.74 C47.1@-3893.7,336.61 ; C47.1@-3902.56,327.76 C47.1@-3893.7,336.61 ; R61.1@-3834.65,336.61 C47.1@-3893.7,336.61
  Bottom w15.75: v1(-3734.25,370.08) v1(-3734.25,435.04)
VDD10: C41.1 C42.1 C43.1 C44.1 U7.9 U7.16 U7.23 | length 748.8
  Top w11.81: C44.1@-3809.06,450.79 -3792.82,450.79 -3781.01,462.6 v1(-3781.01,482.28) U7.9@-3781.01,505.42 ; C42.1@-3801.18,716.54 -3800.7,716.06 U7.23@-3800.7,662.9 ; U7.16@-3692.43,594 -3649.12,594 C43.1@-3641.73,586.61
  Top w15.75: C41.1@-3838.58,716.54 v1(-3820.87,716.54) C42.1@-3801.18,716.54 ; C43.1@-3641.73,586.61 v1(-3641.73,602.36)
  Bottom w15.75: v1(-3820.87,716.54) -3657.48,716.54 -3641.73,700.79 v1(-3641.73,602.36) -3641.73,535.43 -3694.88,482.28 v1(-3781.01,482.28)
VDD10_UPS: C45.1 C46.1 U7.12 | length 132.6
  Top w11.81: U7.12@-3721.96,505.42 -3721.96,478.35 -3681.1,437.49 C45.1@-3681.1,435.04
  Top w19.68: C45.1@-3681.1,435.04 C46.1@-3635.83,435.04
VDD33: C35.1 C36.1 C37.1 C38.1 R58.2 R59.2 R60.2 U7.1 U7.10 U7.13 | length 1116.6
  Top w11.81: C36.1@-3913.39,633.86 -3912.9,633.37 v1(-3895.67,633.37) U7.1@-3849.91,633.37 ; U7.10@-3761.33,505.42 -3761.33,442.91 -3755.91,437.49 C37.1@-3755.91,435.04 ; U7.13@-3692.43,534.95 -3675.2,534.95 -3655.99,515.75 R59.2@-3643.7,515.75
  Top w15.75: v1(-3771.65,435.04) C37.1@-3755.91,435.04 ; v1(-3627.95,726.38) -3618.11,726.38 -3610.24,718.5 R58.2@-3610.24,700.79 R60.2@-3570.87,700.79
  Top w19.68: R59.2@-3643.7,515.75 v1(-3625.98,515.75) C35.1@-3606.3,515.75 C38.1@-3559.06,515.75
  Bottom w15.75: v1(-3895.67,633.37) -3844.49,684.55 -3844.49,724.41 -3830.71,738.19 -3639.76,738.19 v1(-3627.95,726.38) -3620.08,718.5 -3620.08,521.65 v1(-3625.98,515.75) -3681.1,460.63 -3763.78,460.63 -3771.65,452.76 v1(-3771.65,435.04)
XIN: U14.3 Y3.3 | length 270.4
  Top w7.87: U14.3@-2486.63,565.35 -2486.63,509.84 -2472.85,496.06 -2324.8,496.06 -2314.96,486.22 Y3.3@-2314.96,452.76
XL1: C30.1 U6.17 Y1.1 | length 141.5
  Top w7.87: Y1.1@-838.58,1905.51 -838.58,1919.29 -812.99,1944.88 C30.1@-812.99,1962.6 -812.99,1980.31 -807.09,1986.22 -785.43,1986.22 -779.53,1992.13 U6.17@-779.53,2009.84
XL2: C31.1 U6.18 Y1.2 | length 128
  Top w7.87: U6.18@-748.03,2009.84 -748.03,1994.09 -775.59,1966.54 C31.1@-775.59,1962.6 -775.59,1944.88 -746.06,1915.35 Y1.2@-746.06,1905.51
XOU: U14.2 Y3.1 | length 173.3
  Top w7.87: U14.2@-2461.03,565.35 -2460.63,564.95 -2460.63,517.72 -2452.76,509.84 -2387.8,509.84 -2377.95,519.68 Y3.1@-2377.95,555.12
XTAL1: C39.1 U7.21 X1.1 | length 309.4
  Top w7.87: U7.21@-3761.33,662.9 -3761.33,685.52 -3751.97,694.88 -3730.31,694.88 -3722.44,702.76 C39.1@-3722.44,716.54 -3687.01,716.54 -3659.45,744.09 -3659.45,822.83 -3614.17,868.11 X1.1@-3604.33,868.11
XTAL2: C40.1 U7.22 X1.3 | length 183.4
  Top w7.87: U7.22@-3781.01,662.9 -3781.01,699.3 C40.1@-3763.78,716.54 -3750,716.54 -3742.13,724.41 -3742.13,773.62 -3710.63,805.12 X1.3@-3706.69,805.12
ZIG_RST: Q4.3 R47.1 U6.40 | length 798.1
  Top w3.94: U6.40@-505.91,2159.45 -438.98,2159.45 -433.07,2153.54 v1(-409.45,2153.54) ; R47.1@-324.8,1773.62 Q4.3@-324.8,1714.57 v1(-297.24,1714.57)
  Bottom w3.94: v1(-409.45,2153.54) -362.2,2153.54 -340.55,2175.2 -328.74,2175.2 -255.91,2102.36 -255.91,1730.31 -271.65,1714.57 v1(-297.24,1714.57)
ZIG_SPI_CLK: CON1.29 U6.44 | length 375.1
  Top w3.94: U6.44@-470.47,2238.19 v1(-440.94,2238.19)
  Bottom w3.94: v1(-440.94,2238.19) -435.04,2244.09 -153.54,2244.09 CON1.29@-114.17,2204.72
ZIG_SPI_CSN: CON1.31 U6.43 | length 497
  Top w3.94: U6.43@-505.91,2222.44 -478.35,2222.44 v1(-468.5,2212.6)
  Bottom w3.94: v1(-468.5,2212.6) -468.5,2279.53 -425.2,2322.83 -153.54,2322.83 CON1.31@-114.17,2283.46
ZIG_SPI_RXD: CON1.27 U6.45 | length 540.4
  Top w3.94: U6.45@-505.91,2253.94 -342.52,2253.94 -330.71,2242.13 v1(-330.71,2202.76)
  Bottom w3.94: v1(-330.71,2202.76) -314.96,2218.5 -292.87,2218.5 -285.43,2211.07 -285.43,2159.45 -216.54,2090.55 -149.61,2090.55 CON1.27@-114.17,2125.98
ZIG_SPI_TXD: CON1.25 U6.46 | length 495.7
  Top w3.94: U6.46@-470.47,2269.68 -446.85,2269.68 -440.94,2263.78 -322.83,2263.78 -301.18,2242.13 v1(-301.18,2204.72)
  Bottom w3.94: v1(-301.18,2204.72) -301.18,2161.42 -222.44,2082.68 -149.61,2082.68 CON1.25@-114.17,2047.24
ZIG_UART_RXD: R42.2 U6.42 | length 110.2
  Top w3.94: U6.42@-505.91,2190.94 -429.13,2190.94 R42.2@-405.51,2214.57
ZIG_UART_TXD: R43.2 U6.41 | length 63.8
  Top w3.94: U6.41@-470.47,2175.2 -430.22,2175.2 -428.25,2177.17 R43.2@-407.48,2177.17
pads on no net: FP1.35 FP1.37 FP1.38 FP1.39 FP1.40 J1.6 J1.12 J1.18 J1.22 J1.28 J1.31 J1.32 J3.14 J3.15 J6.1 J6.2 J6.12 J6.14 J6.16 J6.18 J6.19 J6.20 J6.21 J10.6 J10.7 J10.A8 J10.B8 JP1.0 JP1.0/2 SW2.3 SW3.3 U1.95 U2.5 U2.6 U2.7 U2.8 U2.10 U2.11 U5.4 U5.12 U6.4 U6.5 U6.6 U6.9 U6.10 U6.11 U6.13 U6.14 U6.16 U6.19 U6.25 U6.26 U6.27 U6.29 U6.52 U6.54 U6.56 U6.57 U6.58 U6.59 U6.60 U6.61 U7.20 U8.8 U8.9 U8.10 U8.11 U8.12 U8.14 U10.3 U10.4 U11.3 U11.7 U12.1 U12.2 U12.3 U12.4 U12.5 U12.6 U12.7 U12.8 U12.9 U12.10 U12.11 U12.12 U12.13 U12.14 U12.15 U12.16 U12.17 U12.18 U12.19 U12.20 U12.21 U12.22 U12.23 U12.24 U12.25 U12.26 U12.27 U12.28 U12.29 U12.30 U12.31 U12.32 U12.33 U12.34 U12.35 U12.36 U12.37 U12.38 U12.39 U12.40 U12.41 U12.42 U12.43 U12.44 U12.45 U12.46 U12.47 U12.48 U12.49 U12.50 U12.51 U12.52 U12.53 U12.54 U12.55 U12.56 U12.57 U12.58 U12.59 U12.60 U12.61 U12.62 U12.63 U12.64 U12.65 U12.66 U12.67 U12.68 U12.69 U12.70 U12.71 U12.72 U12.73 U12.74 U12.75 U12.76 U12.77 U12.78 U12.79 U12.80 U12.81 U12.82 U12.83 U12.84 U12.85 U12.86 U12.87 U12.88 U12.89 U12.90 U12.91 U12.92 U12.93 U12.94 U12.95 U12.96 U12.97 U12.98 U12.99 U12.100 U12.101 U12.102 U12.103 U12.104 U12.105 U12.106 U12.107 U12.108 U12.109 U12.110 U12.111 U12.112 U12.113 U12.114 U12.115 U12.116 U12.117 U12.118 U12.119 U12.120 U12.121 U12.122 U12.123 U12.124 U12.125 U12.126 U12.127 U12.128 U12.129 U12.130 U12.131 U12.132 U12.133 U12.134 U12.135 U12.136 U12.137 U12.138 U12.139 U12.140 U12.141 U12.142 U12.143 U12.144 U12.145 U12.146 U12.147 U12.148 U12.149 U12.150 U12.151 U12.152 U12.153 U12.154 U12.155 U12.156 U12.157 U12.158 U12.159 U12.160 U12.161 U12.162 U12.163 U12.164 U12.165 U12.166 U12.167 U12.168 U12.169 U14.23 U14.24 U14.25 U14.27

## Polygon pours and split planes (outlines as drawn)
5V on Power "Power-5V" (solid, remove dead copper, pour order 0): -3718.5,2273.62 -3391.73,2273.62 -3391.73,854.33 -3220.47,683.07 -3033.46,683.07 -2970.47,746.06 -814.96,746.06 -761.81,799.21 -761.81,2637.8 -47.24,2637.8 -47.24,346.46 -360.24,33.46 -3584.65,33.46 -3645.67,94.49 -3645.67,1106.3 -3718.5,1179.13
GND on Power "Power-GND" (solid, remove dead copper, pour order 6): -2269.69,27.56 -2220.47,27.56 -2220.47,-25.59 -2269.69,-25.59
GND on Power "Power-GND 1" (solid, remove dead copper, pour order 8): -3588.58,27.56 -2255.91,27.56 -2255.91,-25.59 -4750,-25.59 -4750,2978.35 25.59,2978.35 25.59,-25.59 -2238.19,-25.59 -2238.19,27.56 -356.3,27.56 -41.34,342.52 -41.34,2643.7 -767.72,2643.7 -767.72,803.15 -816.93,753.94 -2972.44,753.94 -3037.4,688.98 -3218.5,688.98 -3385.83,856.3 -3385.83,2279.53 -3724.41,2279.53 -3724.41,1173.23 -3651.57,1100.39 -3651.57,90.55
GND on Top "Top-GND" (solid, remove dead copper, pour order 2): -4734.25,2962.6 9.84,2962.6 9.84,-9.84 -4734.25,-9.84
GND on Bottom "Bottom-GND" (solid, remove dead copper, pour order 4): 33.46,-33.46 -4757.87,-33.46 -4757.87,2986.22 33.46,2986.22
GND on GND (split plane): -3624.05,10.09 -3643.66,10.09 -3643.66,283.43 -3624.05,283.43
GND on GND (split plane): -3647.68,10.09 -3671.22,10.09 -3671.22,283.43 -3647.68,283.43
GND on GND (split plane): -3580.75,10.09 -3620.04,10.09 -3620.04,283.43 -3580.75,283.43
DGND on GND (split plane): -3580.75,629.92 -3580.59,629.15 -3580.16,628.5 -3505.94,554.29 -3505.94,297.28 -3927.13,297.28 -3927.13,834.61 -3812.99,834.61 -3812.22,834.76 -3811.57,835.19 -3717.67,929.1 -3580.75,929.1
GND on GND (split plane): -10.09,10.09 -3576.73,10.09 -3576.73,283.43 -3494.09,283.43 -3493.33,283.58 -3492.68,284.01 -3492.24,284.66 -3492.09,285.43 -3492.09,559.06 -3492.24,559.82 -3492.68,560.47 -3566.89,634.69 -3566.89,940.94 -3567.04,941.71 -3567.48,942.36 -3568.13,942.8 -3568.9,942.95 -3724.41,942.95 -3725.18,942.8 -3725.83,942.36 -3819.73,848.46 -3938.98,848.46 -3939.74,848.31 -3940.4,847.88 -3940.83,847.22 -3940.98,846.46 -3940.98,285.43 -3940.83,284.66 -3940.4,284.01 -3939.74,283.58 -3938.98,283.43 -3675.24,283.43 -3675.24,10.09 -4714.32,10.09 -4714.32,2942.67 -10.09,2942.67

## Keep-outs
Top:
  region: -3381.89,2663.39 -3110.24,2663.39 -3110.24,2395.67 -3381.89,2395.67 -3381.89,2663.39
  region: -639.76,1557.09 -639.76,1391.73 -572.83,1391.73 -572.83,1557.09 -639.76,1557.09
  region: -1057.09,253.94 -919.29,254.32 -903.86,252.8 -889.01,248.3 -875.33,240.98 -863.34,231.14 -853.5,219.15 -846.19,205.48 -841.69,190.63 -840.17,175.2 -840.55,175.2 -840.94,137.8 -839.41,130.11 -835.06,123.6 -828.55,119.25 -820.87,117.72 -820.87,118.11 -694.88,118.11 -683.07,129.92 -566.93,129.92 -566.93,70.87 -685.04,70.87 -692.91,78.74 -844.49,78.33 -856.82,79.96 -868.31,84.72 -878.18,92.29 -885.76,102.16 -890.52,113.65 -892.14,125.98 -891.73,125.98 -891.35,135.83 -892.87,143.51 -897.23,150.02 -903.74,154.37 -911.42,155.9 -911.42,155.51 -1057.09,155.51 -1057.09,253.94
  region: -4311.02,2251.97 -4051.18,2251.97 -4051.18,1976.38 -4311.02,1976.38 -4311.02,2251.97
GND:
  region: -1057.09,253.94 -919.29,254.32 -903.86,252.8 -889.01,248.3 -875.33,240.98 -863.34,231.14 -853.5,219.15 -846.19,205.48 -841.69,190.63 -840.17,175.2 -840.55,175.2 -840.94,137.8 -839.41,130.11 -835.06,123.6 -828.55,119.25 -820.87,117.72 -820.87,118.11 -694.88,118.11 -683.07,129.92 -566.93,129.92 -566.93,70.87 -685.04,70.87 -692.91,78.74 -844.49,78.33 -856.82,79.96 -868.31,84.72 -878.18,92.29 -885.76,102.16 -890.52,113.65 -892.14,125.98 -891.73,125.98 -891.35,135.83 -892.87,143.51 -897.23,150.02 -903.74,154.37 -911.42,155.9 -911.42,155.51 -1057.09,155.51 -1057.09,253.94
Keep-Out Layer:
  region: -4844.49,812.99 -3938.98,812.99 -3938.98,-45.28 -4844.49,-45.28 -4844.49,812.99
  lines w3.94: -4724.41,0 0,0 0,2952.76 -4724.41,2952.76 -4724.41,0 ; -4665.35,1688.98 -4594.49,1688.98 -4594.49,1759.84 -4665.35,1759.84 -4665.35,1688.98 ; -4122.05,954.72 -3665.35,954.72 -3665.35,1102.36 -4122.05,1102.36 -4122.05,954.72 ; -3340.55,891.73 -3340.55,1342.52 -3259.84,1342.52 -3259.84,1834.65 -3000,1834.65 -3000,1673.23 -2592.52,1673.23 -2592.52,1289.37 -2891.73,1289.37 -2891.73,891.73 -3340.55,891.73 ; -2570.87,1346.46 -2379.92,1346.46 -2379.92,1541.34 -2570.87,1541.34 -2570.87,1346.46 ; -2338.58,1088.58 -2137.8,1088.58 -2137.8,1251.97 -2338.58,1251.97 -2338.58,1088.58 ; -1944.88,1129.92 -889.76,1129.92 -889.76,1253.94 -1944.88,1253.94 -1944.88,1129.92

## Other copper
Top:
  region net DGND: -3527.56,545.28 -3527.56,488.19 -3470.47,488.19 -3470.47,545.28 -3527.56,545.28
  region net DGND: -3860.24,726.38 -3923.23,726.38 -3923.23,690.94 -3860.24,690.94 -3860.24,726.38
  region net N80464317: -1891.73,425.2 -1842.52,425.2 -1842.52,289.37 -1891.73,289.37 -1891.73,425.2
  region net VCC3V3_SYS: -1025.59,393.7 -891.73,393.7 -891.73,332.68 -1025.59,332.68 -1025.59,393.7
  region net 5V: -3657.48,2269.68 -3746.06,2269.68 -3746.06,2131.89 -3657.48,2131.89 -3657.48,2269.68
  region net USBVBUS: -2183.07,372.05 -2125.98,372.05 -2125.98,309.06 -2183.07,309.06 -2183.07,372.05
  region net N80396542: -3791.34,2263.78 -4096.46,2263.78 -4114.17,2246.06 -4114.17,1978.35 -4106.3,1970.47 -4106.3,1868.11 -4116.14,1858.27 -4151.57,1858.27 -4151.57,1846.46 -4005.91,1846.46 -3992.13,1860.24 -3992.13,2120.08 -3974.41,2137.8 -3791.34,2137.8 -3791.34,2263.78
  region net 5V: -2629.92,403.54 -2647.64,403.54 -2647.64,332.68 -2661.42,318.9 -2661.42,261.81 -2657.48,257.87 -2657.48,228.35 -2610.24,228.35 -2610.24,265.75 -2629.92,285.43 -2629.92,403.54
  region net DGND: -3706.69,415.35 -3614.17,415.35 -3614.17,362.2 -3706.69,362.2 -3706.69,415.35
  region net HOST1-5V: -3710.63,1435.04 -3651.57,1435.04 -3651.57,1312.99 -3710.63,1312.99 -3710.63,1435.04
  region net 5V: -3460.63,1374.02 -3616.14,1374.02 -3616.14,1312.99 -3460.63,1312.99 -3460.63,1374.02
  region net 5V: -2799.21,291.34 -2757.87,291.34 -2757.87,251.97 -2799.21,251.97 -2799.21,291.34
  region net N80396572: -4187.01,1834.65 -4200.79,1834.65 -4200.79,1903.54 -4206.69,1909.45 -4206.69,1956.69 -4226.38,1976.38 -4324.8,1976.38 -4344.49,1996.06 -4344.49,2222.44 -4175.2,2222.44 -4175.2,1875.98 -4187.01,1864.17 -4187.01,1834.65
  region net 5V: -3551.18,1505.91 -3551.18,1433.07 -3468.5,1433.07 -3468.5,1505.91 -3551.18,1505.91
  region net 5V: -2224.41,574.8 -2127.95,574.8 -2127.95,403.54 -2224.41,403.54 -2224.41,574.8
  region net 5V: -612.2,1877.95 -553.15,1877.95 -549.21,1881.89 -549.21,2023.62 -568.9,2023.62 -568.9,1970.47 -612.2,1927.17 -612.2,1877.95
  region net N80398618: -513.78,2023.62 -537.4,2023.62 -537.4,1887.8 -501.97,1887.8 -501.97,1970.47 -513.78,1982.28 -513.78,2023.62
  region net 5V: -572.83,1663.39 -492.13,1663.39 -492.13,1344.49 -572.83,1344.49 -572.83,1663.39
  region net DC-12V: -4206.69,1850.39 -4226.38,1850.39 -4226.38,1787.4 -4242.13,1771.65 -4318.9,1771.65 -4324.8,1765.75 -4324.8,1692.91 -4336.61,1681.1 -4438.98,1681.1 -4438.98,1545.28 -4183.07,1545.28 -4183.07,1773.62 -4206.69,1797.24 -4206.69,1850.39
  region net N80413519: -700.79,1555.12 -639.76,1555.12 -639.76,1346.46 -742.13,1346.46 -763.78,1368.11 -763.78,1440.94 -757.87,1446.85 -706.69,1446.85 -700.79,1452.76 -700.79,1555.12
  region net LED+: -777.56,1665.35 -708.66,1665.35 -708.66,1507.87 -777.56,1507.87 -777.56,1665.35
  region net 5V: -2450.79,783.46 -2521.65,783.46 -2521.65,681.1 -2450.79,681.1 -2450.79,783.46
  region net DGND: -3669.29,415.35 -3897.64,415.35 -3897.64,383.86 -3669.29,383.86 -3669.29,415.35
  region net VCC3V3_SYS: -921.26,379.92 -858.27,379.92 -858.27,332.68 -921.26,332.68 -921.26,379.92
  region net LED-: -970.47,2015.75 -1041.34,2015.75 -1041.34,1877.95 -970.47,1877.95 -970.47,2015.75
  region net VCC3V3_SYS: -2027.56,423.23 -1952.76,423.23 -1952.76,375.98 -2027.56,375.98 -2027.56,423.23
  region net DGND: -3631.89,828.74 -3574.8,828.74 -3574.8,763.78 -3631.89,763.78 -3631.89,828.74
  region net DGND: -3750,891.73 -3679.13,891.73 -3679.13,844.49 -3750,844.49 -3750,891.73
  region net DGND: -3923.23,539.37 -3923.23,383.86 -3830.71,383.86 -3830.71,460.63 -3838.58,468.5 -3838.58,539.37 -3923.23,539.37
  region net DGND: -3722.44,931.1 -3667.32,931.1 -3667.32,844.49 -3722.44,844.49 -3722.44,931.1
  region net N80464332: -2029.53,334.65 -1901.57,334.65 -1901.57,165.35 -2029.53,165.35 -2029.53,334.65
  region net VCC1: -425.2,1968.5 -425.2,1799.21 -470.47,1799.21 -470.47,1968.5 -425.2,1968.5
Bottom:
  region net VCC3V3_SYS: -1960.63,421.26 -1990.16,421.26 -1990.16,381.89 -1960.63,381.89 -1960.63,421.26
GND (plane layer: these items are gaps in the copper):
  region: -3568.9,633.86 -3494.09,559.06 -3494.09,285.43 -3938.98,285.43 -3938.98,846.46 -3818.9,846.46 -3724.41,940.94 -3568.9,940.94 hole: -3578.74,931.1 -3718.5,931.1 -3812.99,836.61 -3929.13,836.61 -3929.13,295.28 -3503.94,295.28 -3503.94,555.12 -3578.74,629.92
  lines w3.94: -4742.13,-17.72 -3645.67,-17.72 -3645.67,285.43 -3938.98,285.43 -3938.98,846.46 -3818.9,846.46 -3724.41,940.94 -3568.9,940.94 -3568.9,633.86 -3494.09,559.06 -3494.09,285.43 -3622.05,285.43 -3622.05,-17.72 17.72,-17.72 17.72,2970.47 -4742.13,2970.47 -4742.13,-17.72 ; -3929.13,295.28 -3929.13,836.61 -3812.99,836.61 -3718.5,931.1 -3578.74,931.1 -3578.74,629.92 -3503.94,555.12 -3503.94,295.28 -3929.13,295.28 ; -3673.23,-17.72 -3578.74,-17.72 -3578.74,285.43 -3673.23,285.43 -3673.23,-17.72

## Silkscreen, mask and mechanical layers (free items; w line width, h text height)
Silkscreen Top:
  lines w10: -4724.41,-3.94 -4125.98,-3.94 -4125.98,940.94 -4724.41,940.94 -4724.41,-3.94 ; -921.26,3.94 19.69,3.94 19.69,1110.24 -921.26,1110.24 -921.26,3.94
  text "MASKROM" at -2025.59,2316.93 h50
  text "2020-04-11" at -1769.69,2177.17 h50
  text "3308_SHAJIN_v1.0" at -1826.77,2074.8 h50
  text "30" at -1931.1,2000 h50
  text "1" at -1960.63,809.06 h50
  text "120" at -2222.44,631.89 h50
